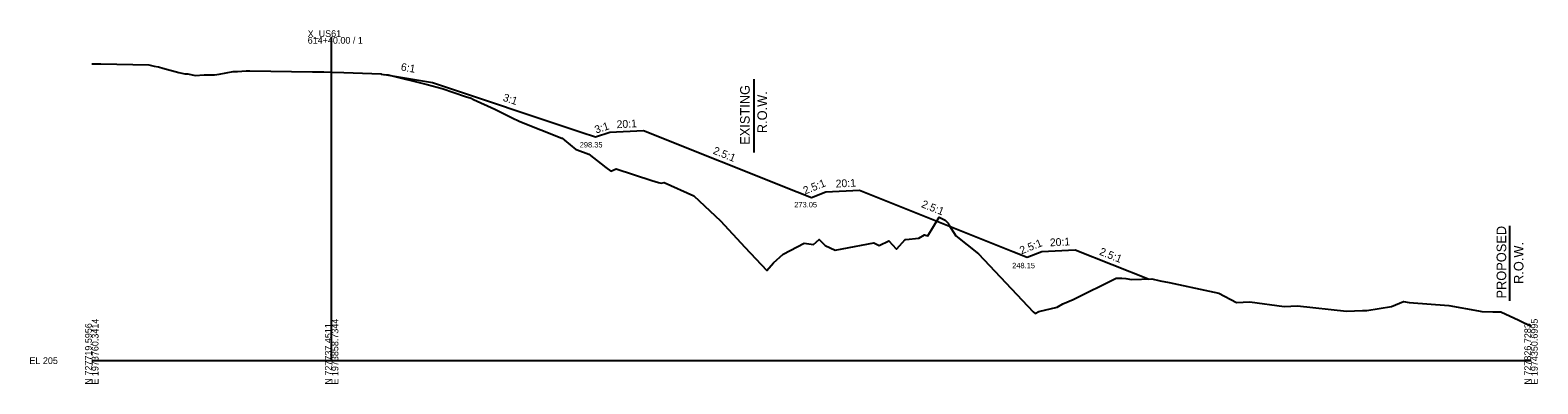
# Model space of a CAD drawing. Extents: x -26 to 1604, y -13 to 9623.
# Drawn here: x -26 to 603, y 5990 to 6138 of the extents above; entities that cross this region are included whole.
import ezdxf

# ---------------------------------------------------------------- set-up
doc = ezdxf.new("R2010")
doc.units = 0
for name, color, linetype in [('Draft_XS_Grid', 7, 'Continuous'), ('DTM_X_GROUND', 7, 'Continuous'), ('SLOPE_STAKES_FILL', 7, 'Continuous'), ('XS_CELL', 7, 'Continuous'), ('XS_P_GROUND', 7, 'Continuous'), ('XS_P_ROW', 7, 'Continuous'), ('XS_P_TX_DCH', 7, 'Continuous'), ('XS_P_TX_FS_BS', 7, 'Continuous'), ('XS_X_ROW', 7, 'Continuous')]:
    doc.layers.add(name, color=color, linetype=linetype)

msp = doc.modelspace()

# ---------------------------------------------------------------- linework, layer by layer
at = {"layer": 'DTM_X_GROUND'}
msp.add_lwpolyline([(0, 6123.8), (3.78, 6123.72), (23.79, 6123.31), (25.94, 6122.87), (27.82, 6122.52), (29.56, 6121.96), (36.32, 6120.22), (38.84, 6119.61), (40.01, 6119.68), (43.09, 6118.91), (46.81, 6119.19), (49.82, 6119.17), (51.1, 6119.2), (52.08, 6119.35), (53.15, 6119.54), (58.92, 6120.64), (59.25, 6120.64), (60.7, 6120.61), (64.29, 6120.82), (65.31, 6120.86), (65.95, 6120.88), (92.08, 6120.49), (94.7, 6120.45), (95.02, 6120.43), (96.79, 6120.41), (100.06, 6120.38), (105.09, 6120.16), (120.65, 6119.57), (120.66, 6119.51), (121.6, 6119.4), (123.52, 6119.16), (139.8, 6115.12), (146.09, 6113.56), (155.82, 6110.21), (158.12, 6109.41), (159.16, 6108.94), (168.03, 6104.85), (174.93, 6101.46), (178.41, 6099.79), (195.97, 6092.79), (196.03, 6092.74), (196.05, 6092.73), (197.07, 6091.91), (201.79, 6088.01), (202.34, 6087.93), (207.22, 6086.16), (214.28, 6080.5), (216.39, 6079.01), (218.54, 6079.93), (233.54, 6075.12), (236.32, 6074.31), (237.35, 6074.05), (238.58, 6074.25), (251.03, 6068.68), (262.05, 6058.34), (272.28, 6047.26), (281.48, 6037.65), (284.26, 6040.8), (288.18, 6044.38), (296.95, 6049.01), (300.81, 6048.39), (303.22, 6050.56), (305.68, 6048.03), (309.91, 6046.04), (312.89, 6046.6), (326.06, 6049.06), (328.25, 6048.03), (332.28, 6050.03), (335.29, 6046.61), (335.58, 6046.65), (339.15, 6050.53), (339.38, 6050.51), (344.76, 6051.08), (347.16, 6052.41), (348.59, 6052.08), (353.3, 6059.8), (355.8, 6058.6), (357.18, 6057.24), (357.33, 6056.63), (360.21, 6052.09), (369.62, 6044.55), (392.5, 6020.31), (393.22, 6019.65), (394.83, 6020.47), (402.4, 6022.23), (404.78, 6023.7), (409.12, 6025.5), (427.1, 6034.4), (429.36, 6034.34), (431.05, 6034.3), (433.46, 6033.8), (441.92, 6034.08), (445.37, 6033.33), (449.1, 6032.52), (465.93, 6028.96), (469.78, 6028.12), (477.24, 6024.22), (482.76, 6024.57), (497.02, 6022.61), (502.66, 6022.9), (523.02, 6020.63), (526.46, 6020.76), (529.71, 6020.88), (531.5, 6020.95), (541.82, 6022.56), (546.86, 6024.72), (549.18, 6024.26), (565.72, 6023.05), (578.03, 6020.78), (579.43, 6020.47), (584.06, 6020.32), (587.36, 6020.37), (594.93, 6016.83), (600, 6014.4)], dxfattribs=at)
at = {"layer": 'XS_CELL'}
for p, q in [((100, 6000), (100, 6135)), ((0, 6000), (100, 6000)), ((100, 6000), (600, 6000))]:
    msp.add_line(p, q, dxfattribs=at)
at = {"layer": 'XS_P_GROUND'}
for points in [[(122, 6119.35), (142, 6116.01)], [(142, 6116.01), (204, 6095.35), (210, 6093.35), (216, 6095.35), (230, 6096.05), (294, 6070.45), (300, 6068.05), (306, 6070.45), (320, 6071.15), (384, 6045.55), (390, 6043.15), (396, 6045.55), (410, 6046.25), (440.77, 6033.94)]]:
    msp.add_lwpolyline(points, dxfattribs=at)
at = {"layer": 'XS_P_ROW'}
msp.add_line((591, 6056.27), (591, 6025), dxfattribs=at)
at = {"layer": 'XS_X_ROW'}
msp.add_line((276, 6117.35), (276, 6086.81), dxfattribs=at)

# ---------------------------------------------------------------- texts
at = {"layer": 'Draft_XS_Grid'}
msp.add_text('-', height=0.0001, dxfattribs=at).set_placement((0, 6000))
at = {"layer": 'SLOPE_STAKES_FILL'}
for p in [(141.96, 6115.95), (203.96, 6095.29), (209.96, 6093.29), (215.96, 6095.29), (229.96, 6095.99), (293.96, 6070.39), (299.96, 6067.99), (305.96, 6070.39), (319.96, 6071.09), (383.96, 6045.49), (389.96, 6043.09), (395.96, 6045.49), (409.96, 6046.19)]:
    msp.add_text('X', height=0.12, dxfattribs=at).set_placement(p)
at = {"layer": 'XS_CELL'}
for s, p in [('X_US61', (90, 6135)), ('614+40.00 / 1', (90, 6132.2)), ('EL 205', (-26, 5998.6))]:
    msp.add_text(s, height=2.8, dxfattribs=at).set_placement(p)
for s, p in [('N 727719.5956', (0, 5990)), ('E 1973760.3414', (2.8, 5990)), ('N 727737.4511', (100, 5990)), ('E 1973858.7344', (102.8, 5990)), ('N 727826.7283', (600, 5990)), ('E 1974350.6995', (602.8, 5990))]:
    msp.add_text(s, height=2.8, rotation=90, dxfattribs=at).set_placement(p)
at = {"layer": 'XS_P_GROUND'}
for p in [(121.96, 6119.29), (440.73, 6033.88)]:
    msp.add_text('X', height=0.12, dxfattribs=at).set_placement(p)
at = {"layer": 'XS_P_ROW'}
for s, p in [('PROPOSED', (589.64, 6025.89)), ('R.O.W.', (596.84, 6031.96))]:
    msp.add_text(s, height=4, rotation=90, dxfattribs=at).set_placement(p)
at = {"layer": 'XS_P_TX_DCH'}
for s, p in [('298.35', (203.41, 6088.91)), ('273.05', (292.85, 6063.92)), ('248.15', (383.69, 6038.53))]:
    msp.add_text(s, height=2.25, dxfattribs=at).set_placement(p)
at = {"layer": 'XS_P_TX_FS_BS'}
for s, rotation, p in [('6:1', 350.53766, (128.68, 6121.03)), ('3:1', 341.56507, (171.12, 6108.45)), ('3:1', 18.43493, (210.24, 6094.67)), ('20:1', 2.86241, (218.88, 6096.93)), ('2.5:1', 338.19859, (258.7, 6086.39)), ('2.5:1', 21.80141, (297.32, 6069.26)), ('20:1', 2.86241, (310.2, 6072.18)), ('2.5:1', 338.19859, (345.57, 6064.09)), ('2.5:1', 21.80141, (387.58, 6044.29)), ('20:1', 2.86241, (399.49, 6047.66)), ('2.5:1', 338.19859, (419.74, 6044.28))]:
    msp.add_text(s, height=3.24, rotation=rotation, dxfattribs=at).set_placement(p)
at = {"layer": 'XS_X_ROW'}
for s, p in [('EXISTING', (274.29, 6090.01)), ('R.O.W.', (281.49, 6094.85))]:
    msp.add_text(s, height=4, rotation=90, dxfattribs=at).set_placement(p)

doc.saveas('drawing.dxf')
